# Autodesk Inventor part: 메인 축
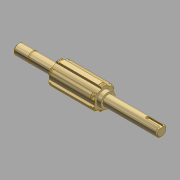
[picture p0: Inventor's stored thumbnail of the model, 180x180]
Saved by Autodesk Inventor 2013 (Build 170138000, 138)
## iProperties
Created: 2015-11
Part Number: 메인 축
Document SubType Name: 모델링
Designer: mdu
Mass: 21.4462 g
Surface Area: 72.5109 cm^2
Volume: 21.4462 cm^3
Density: 1 g/cm^3
Material: 강철, 연강
변환 표준: STEP AP214IS
파일 이름: C:\Users\SeoGD\Desktop\?쒗뿕\硫붿씤 異?.stp
전처리기: Build: 253, Release: 2010 SP1 - Date: Wed 07/29/2009
전송 단위: 밀리미터
불확실성: 0.01
Author: mdu
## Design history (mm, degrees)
sketch "스케치1"
  geometry: L1 (-69.5, 0)-(69.5, 0); L2 (69.5, 0)-(69.5, 5); L3 (69.5, 5)-(55.5, 5); L4 (55.5, 5)-(55.5, 4.8); L5 (55.5, 4.8)-(54.35, 4.8); L6 (54.35, 4.8)-(54.35, 5); L7 (54.35, 5)-(30.5, 5); L8 (30.5, 5)-(30.5, 9); L9 (30.5, 9)-(-13.5, 9); L10 (-13.5, 9)-(-13.5, 7); L11 (-13.5, 7)-(-17.5, 7); L12 (-17.5, 7)-(-17.5, 5); L13 (-17.5, 5)-(-69.5, 5); L14 (-69.5, 5)-(-69.5, 0); 2 further points
  constraints: 28 end point, 9 parallel, 4 collinear, 2 perpendicular, 1 coincident, 1 horizontal, 1 midpoint
  dimensions: "d2" = 1.15 distance between parallel lines of L6 L4; "d3" = 10 diameter of L3 L1; "d4" = 9.6 diameter of L5 L1; "d6" = 44 distance between parallel lines of L10 L8; "d7" = 4 distance between parallel lines of L12 L10; "d8" = 14 diameter of L11 L1; "d9" = 18 diameter of L9 L1; "d33" = 52 distance from line of L12.end L14; "d37" = 39 distance between parallel lines of L8 L2; "d38" = 14 distance between parallel lines of L2 L4
revolve "회전1" sketch "스케치1" stored, may be unused: angle "d10" = 90 deg
sketch "스케치2"
  geometry: L1 (2.5, 10.712)-(2.5, 8.646); L2 (-2.5, 10.712)-(-2.5, 8.646); A1 r 9 centre (0, 0) between (2.5, 8.646) and (-2.5, 8.646) reference; A2 r 11 centre (0, 0) between (2.5, 10.712) and (-2.5, 10.712); 1 further point
  constraints: 4 end point, 4 point on circle, 2 parallel, 1 centre point, 1 coincident, 1 vertical
  dimensions: "d11" = 22 diameter of A2; "d12" = 5 distance between parallel lines of L1 L2
extrude "돌출1" join sketch "스케치2" stored distance "d13" = 10; taper "d14" = 0 deg
chamfer "모따기1" distance "d15" = 1; stored, may be unused: second distance "d16" = 2, angle "d17" = 45 deg
node "작업 평면1"
node "작업 평면2"
sketch "스케치3"
  geometry: L1 (2.5, 10.712)-(2.5, 10.198); L2 (-2.5, 10.712)-(-2.5, 10.198); A1 r 11 centre (0, 0) between (2.5, 10.712) and (-2.5, 10.712) reference; A2 r 10.5 centre (0, 0) between (2.5, 10.198) and (-2.5, 10.198); 1 further point
  constraints: 4 end point, 2 point on circle, 1 centre point, 1 coincident, 1 parallel, 1 vertical
  dimensions: "d19" = 21 diameter of A2
extrude "돌출2" cut sketch "스케치3" distance "d20" = 1.35; taper "d21" = 0 deg
node "작업 평면3"
sketch "스케치4"
  geometry: L1 (-26, -5)-(-26, 5) reference; L2 (-26, 1.5)-(-12.5, 1.5); L3 (-12.5, -1.5)-(-26, -1.5); A1 r 1.5 centre (-12.5, 0) between (-12.5, -1.5) and (-12.5, 1.5); 2 further points
  constraints: 4 end point, 2 perpendicular, 2 point on circle, 2 point on line, 2 tangent, 1 centre point, 1 horizontal alignment, 1 midpoint
  dimensions: "d25" = 3 distance between parallel lines of L3 L2; "d26" = 15 dimension on A1 L1
extrude "돌출3" cut sketch "스케치4" distance "d27" = 1.8; taper "d28" = 0 deg
chamfer "모따기2" distance "d29" = 1; stored, may be unused: second distance "d30" = 2, angle "d31" = 45 deg
node "솔리드1"
node "솔리드 본체"
node "곡면 본체"
mirror "대칭1"
pattern_circular "원형 패턴1" dims "d23" = 360 deg
node "솔리드2"
other parameters: "d18" = -1.65
